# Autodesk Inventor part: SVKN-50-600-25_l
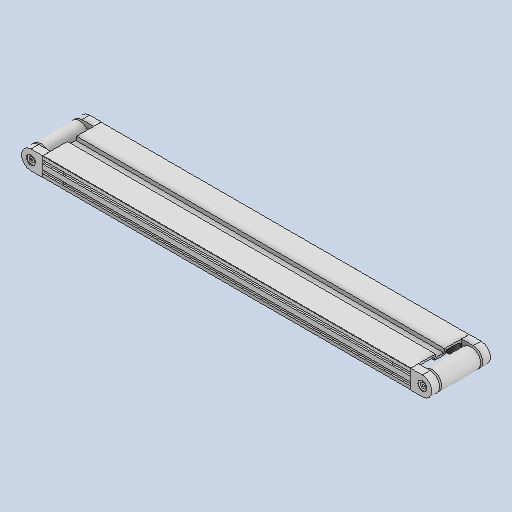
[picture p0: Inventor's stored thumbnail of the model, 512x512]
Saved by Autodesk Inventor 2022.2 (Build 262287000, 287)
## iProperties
Created: 2024-10
Part Number: SVKN-50-600-25_l
Material: Generico
Document SubType Name: Modeling
Designer: 18907419
Density: 1 g/cm^3
Appearance: Default
Author: 18907419
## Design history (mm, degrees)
feature "Solido1"
node "Solido2"
